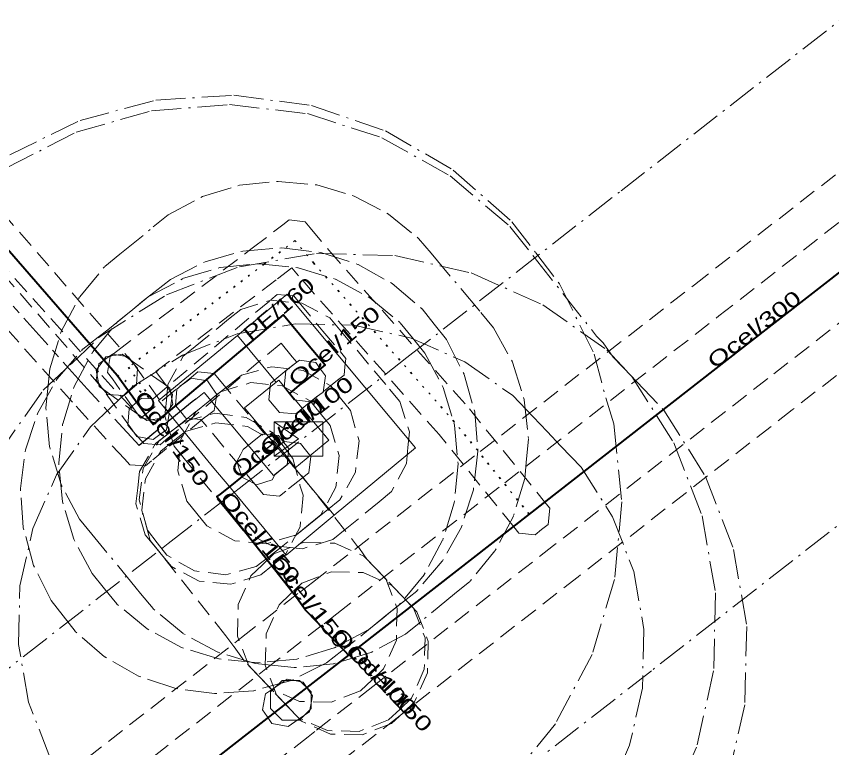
# Model space of a CAD drawing. Extents: x -588392 to -586332, y -1208963 to -1206334.
# Drawn here: x -587903.38 to -587862.35, y -1206828.1 to -1206791.27 of the extents above; entities that cross this region are included whole.
import ezdxf

# ---------------------------------------------------------------- set-up
doc = ezdxf.new("R2010")
doc.units = 0
doc.header["$LTSCALE"] = 0.3
for name, pattern in [('DOT_DASHED', [7.7, 5, -1.2, 0.3, -1.2]), ('DOTTED', [1.5, 0.3, -1.2]), ('LONG_DASH_SHORT_DASH', [9.9, 6, -1.2, 1.5, -1.2]), ('MEDIUM_DASHED', [4.5, 3, -1.5])]:
    doc.linetypes.add(name, pattern=pattern)
for name, color, linetype, lineweight in [('1', 7, 'MEDIUM_DASHED', 13), ('11', 7, 'MEDIUM_DASHED', 13), ('24', 7, 'Continuous', 25), ('3', 7, 'DOT_DASHED', 13), ('31', 7, 'Continuous', 13), ('34', 7, 'Continuous', 40), ('35', 7, 'Continuous', 35), ('51', 7, 'MEDIUM_DASHED', 13), ('54', 7, 'Continuous', 13), ('55', 7, 'LONG_DASH_SHORT_DASH', 25), ('56', 7, 'DOTTED', 35), ('59', 7, 'Continuous', 13), ('7', 7, 'MEDIUM_DASHED', 13), ('8', 7, 'MEDIUM_DASHED', 13)]:
    doc.layers.add(name, color=color, linetype=linetype, lineweight=lineweight)
doc.layers.add('30', color=7, linetype='Continuous')
doc.layers.add('40', color=7, linetype='Continuous')

msp = doc.modelspace()

# ---------------------------------------------------------------- linework, layer by layer
at = {"layer": '1'}
for points in [[(-587903, -1206831.106), (-587892.392, -1206822.823), (-587892.049, -1206822.555), (-587889.13, -1206820.281), (-587888.482, -1206819.776), (-587880.036, -1206813.19), (-587869.26, -1206804.786), (-587825.045, -1206770.304)], [(-587819.53, -1206776.148), (-587864.34, -1206811.094), (-587875.116, -1206819.498), (-587883.564, -1206826.086), (-587884.212, -1206826.591), (-587887.131, -1206828.865)]]:
    msp.add_lwpolyline(points, dxfattribs=at)
for points in [[(-587926.025, -1206775.891), (-587925.751, -1206776.201), (-587925.351, -1206776.654), (-587897.549, -1206808.683), (-587897.277, -1206808.996), (-587897.335, -1206809.823), (-587897.648, -1206810.094), (-587897.961, -1206810.366), (-587898.788, -1206810.308), (-587899.059, -1206809.995), (-587926.857, -1206777.972), (-587927.251, -1206777.525), (-587927.525, -1206777.214), (-587927.473, -1206776.387), (-587927.163, -1206776.113), (-587926.852, -1206775.839)], [(-587897.082, -1206810.493), (-587896.505, -1206810.534), (-587890.574, -1206805.545), (-587890.254, -1206805.276), (-587889.838, -1206805.314), (-587889.423, -1206805.352), (-587889.157, -1206805.675), (-587887.962, -1206807.129), (-587887.077, -1206808.173), (-587886.803, -1206808.496), (-587886.845, -1206808.918), (-587886.886, -1206809.339), (-587887.217, -1206809.602), (-587888.247, -1206810.422), (-587888.571, -1206810.68), (-587889.394, -1206810.587), (-587889.652, -1206810.263), (-587889.91, -1206809.939), (-587889.817, -1206809.116), (-587889.493, -1206808.858), (-587889.27, -1206808.68), (-587889.498, -1206808.411), (-587890.06, -1206807.726), (-587895.836, -1206812.585), (-587896.15, -1206812.849), (-587896.967, -1206812.785), (-587897.236, -1206812.475), (-587897.496, -1206812.175), (-587897.767, -1206811.862), (-587897.708, -1206811.035), (-587897.395, -1206810.764)], [(-587897.732, -1206808.42), (-587897.491, -1206808.756), (-587895.927, -1206810.937), (-587895.686, -1206811.274), (-587895.821, -1206812.092), (-587896.157, -1206812.333), (-587896.494, -1206812.574), (-587897.312, -1206812.439), (-587897.553, -1206812.103), (-587899.117, -1206809.922), (-587899.358, -1206809.585), (-587899.223, -1206808.767), (-587898.887, -1206808.526), (-587898.55, -1206808.285)], [(-587887.939, -1206810.191), (-587888.27, -1206810.44), (-587888.529, -1206810.634), (-587888.998, -1206811.027), (-587889.316, -1206811.293), (-587890.141, -1206811.22), (-587890.407, -1206810.902), (-587890.673, -1206810.584), (-587890.6, -1206809.759), (-587890.282, -1206809.493), (-587889.771, -1206809.066), (-587889.47, -1206808.84), (-587889.139, -1206808.591), (-587888.319, -1206808.709), (-587888.07, -1206809.04), (-587887.821, -1206809.371)], [(-587887.096, -1206815.625), (-587887.72, -1206816.118), (-587888.211, -1206816.506), (-587888.315, -1206816.589), (-587888.671, -1206816.879), (-587889.288, -1206817.382), (-587890.812, -1206817.84), (-587892.395, -1206817.679), (-587893.796, -1206816.925), (-587894.299, -1206816.309), (-587894.802, -1206815.692), (-587895.26, -1206814.168), (-587895.099, -1206812.585), (-587894.345, -1206811.184), (-587893.729, -1206810.681), (-587893.325, -1206810.351), (-587893.171, -1206810.23), (-587892.68, -1206809.842), (-587892.056, -1206809.349), (-587890.525, -1206808.915), (-587888.945, -1206809.1), (-587887.555, -1206809.876), (-587887.062, -1206810.5), (-587886.569, -1206811.124), (-587886.135, -1206812.655), (-587886.32, -1206814.235)], [(-587888.056, -1206816.378), (-587888.673, -1206816.881), (-587890.06, -1206818.011), (-587890.678, -1206818.49), (-587891.307, -1206818.978), (-587892.841, -1206819.398), (-587894.42, -1206819.199), (-587895.802, -1206818.411), (-587896.29, -1206817.782), (-587896.778, -1206817.153), (-587897.198, -1206815.619), (-587896.999, -1206814.04), (-587896.211, -1206812.658), (-587895.582, -1206812.17), (-587895.04, -1206811.749), (-587893.727, -1206810.679), (-587893.11, -1206810.176), (-587891.586, -1206809.72), (-587890.003, -1206809.881), (-587888.602, -1206810.636), (-587888.099, -1206811.253), (-587887.596, -1206811.87), (-587887.14, -1206813.394), (-587887.301, -1206814.977)], [(-587889.47, -1206813.532), (-587889.111, -1206814.88), (-587888.953, -1206815.391), (-587889.102, -1206816.976), (-587889.845, -1206818.382), (-587890.458, -1206818.89), (-587891.071, -1206819.398), (-587892.591, -1206819.867), (-587894.176, -1206819.718), (-587895.582, -1206818.975), (-587896.09, -1206818.362), (-587896.38, -1206818.012), (-587896.901, -1206817.384), (-587897.366, -1206815.82), (-587897.274, -1206815.009), (-587897.182, -1206814.198), (-587896.378, -1206812.778), (-587895.73, -1206812.283), (-587895.56, -1206812.153), (-587894.928, -1206811.67), (-587893.39, -1206811.26), (-587891.813, -1206811.47), (-587890.436, -1206812.268), (-587889.953, -1206812.9)], [(-587892.424, -1206823.023), (-587892.439, -1206823.002), (-587892.842, -1206822.47), (-587896.147, -1206818.291), (-587896.641, -1206817.667), (-587897.075, -1206816.136), (-587896.891, -1206814.556), (-587896.115, -1206813.167), (-587895.491, -1206812.673), (-587894.867, -1206812.179), (-587893.336, -1206811.745), (-587891.756, -1206811.929), (-587890.367, -1206812.705), (-587889.873, -1206813.329), (-587886.518, -1206817.57), (-587886.217, -1206817.967), (-587886.154, -1206818.029), (-587885.896, -1206818.397), (-587885.742, -1206818.612), (-587885.345, -1206819.029), (-587884.796, -1206819.605), (-587884.222, -1206821.089), (-587884.26, -1206822.68), (-587884.904, -1206824.135), (-587885.48, -1206824.684), (-587886.056, -1206825.233), (-587887.54, -1206825.807), (-587889.131, -1206825.769), (-587890.586, -1206825.125), (-587891.135, -1206824.549), (-587891.918, -1206823.728)], [(-587889.181, -1206826.599), (-587889.73, -1206826.023), (-587890.428, -1206825.291), (-587891.136, -1206824.548), (-587891.685, -1206823.972), (-587892.258, -1206822.488), (-587892.219, -1206820.897), (-587891.575, -1206819.442), (-587890.999, -1206818.893), (-587890.423, -1206818.344), (-587888.939, -1206817.771), (-587887.348, -1206817.81), (-587885.893, -1206818.454), (-587885.344, -1206819.03), (-587884.638, -1206819.771), (-587883.94, -1206820.503), (-587883.391, -1206821.079), (-587882.817, -1206822.563), (-587882.855, -1206824.153), (-587883.499, -1206825.609), (-587884.075, -1206826.158), (-587884.651, -1206826.707), (-587886.135, -1206827.281), (-587887.725, -1206827.243)], [(-587889.027, -1206826.765), (-587889.574, -1206826.188), (-587889.738, -1206826.015), (-587890.285, -1206825.438), (-587890.855, -1206823.952), (-587890.812, -1206822.361), (-587890.164, -1206820.907), (-587889.587, -1206820.36), (-587889.01, -1206819.813), (-587887.524, -1206819.243), (-587885.933, -1206819.286), (-587884.479, -1206819.934), (-587883.932, -1206820.511), (-587883.768, -1206820.684), (-587883.221, -1206821.261), (-587882.651, -1206822.747), (-587882.694, -1206824.338), (-587883.342, -1206825.792), (-587883.919, -1206826.339), (-587884.496, -1206826.886), (-587885.982, -1206827.456), (-587887.573, -1206827.413)]]:
    msp.add_lwpolyline(points, close=True, dxfattribs=at)
at = {"layer": '1', "linetype": 'DOT_DASHED'}
for points in [[(-587903.714, -1206798.246), (-587900.178, -1206796.51), (-587896.371, -1206795.496), (-587892.439, -1206795.245), (-587888.534, -1206795.766), (-587884.806, -1206797.038), (-587881.397, -1206799.014), (-587878.44, -1206801.616), (-587877.243, -1206803.181), (-587876.046, -1206804.746), (-587874.31, -1206808.282), (-587873.725, -1206810.478), (-587873.318, -1206811.797), (-587872.914, -1206815.716), (-587873.281, -1206819.638), (-587874.407, -1206823.413), (-587876.248, -1206826.896), (-587878.733, -1206829.953)], [(-587903.872, -1206798.902), (-587900.365, -1206797.108), (-587896.575, -1206796.032), (-587892.648, -1206795.716), (-587888.735, -1206796.173), (-587884.986, -1206797.385), (-587881.546, -1206799.304), (-587878.546, -1206801.858), (-587877.324, -1206803.403), (-587874.183, -1206807.373), (-587873.85, -1206807.706), (-587873.342, -1206808.432), (-587872.404, -1206809.416), (-587870.294, -1206812.743), (-587868.874, -1206816.418), (-587868.199, -1206820.299), (-587868.293, -1206824.238), (-587869.154, -1206828.082), (-587870.749, -1206831.685)], [(-587906.215, -1206828.582), (-587906.881, -1206824.698), (-587906.775, -1206820.76), (-587905.904, -1206816.918), (-587904.3, -1206813.319), (-587902.025, -1206810.103), (-587900.595, -1206808.748), (-587899.165, -1206807.393), (-587895.832, -1206805.292), (-587892.154, -1206803.883), (-587888.27, -1206803.217), (-587884.332, -1206803.323), (-587880.49, -1206804.194), (-587876.891, -1206805.798), (-587873.675, -1206808.073), (-587872.32, -1206809.503), (-587872.156, -1206809.676), (-587870.801, -1206811.106), (-587868.7, -1206814.439), (-587867.291, -1206818.117), (-587866.625, -1206822.001), (-587866.731, -1206825.939), (-587867.602, -1206829.781)], [(-587901.701, -1206828.571), (-587902.765, -1206825.815), (-587903.271, -1206822.904), (-587903.2, -1206819.95), (-587902.554, -1206817.066), (-587901.357, -1206814.365), (-587899.657, -1206811.948), (-587898.587, -1206810.929), (-587897.517, -1206809.91), (-587895.022, -1206808.328), (-587892.266, -1206807.264), (-587889.355, -1206806.758), (-587886.401, -1206806.829), (-587883.517, -1206807.475), (-587880.816, -1206808.672), (-587878.399, -1206810.372), (-587877.38, -1206811.442), (-587876.675, -1206812.182), (-587875.979, -1206812.912), (-587874.96, -1206813.981), (-587873.377, -1206816.476), (-587872.312, -1206819.232), (-587871.804, -1206822.143), (-587871.875, -1206825.097), (-587872.52, -1206827.98), (-587873.715, -1206830.682)]]:
    msp.add_lwpolyline(points, dxfattribs=at)
for points in [[(-587883.227, -1206820.215), (-587884, -1206820.826), (-587884.49, -1206821.213), (-587884.558, -1206821.267), (-587884.879, -1206821.529), (-587885.642, -1206822.152), (-587887.382, -1206823.075), (-587889.269, -1206823.641), (-587891.229, -1206823.828), (-587893.189, -1206823.63), (-587895.073, -1206823.052), (-587896.807, -1206822.118), (-587898.326, -1206820.864), (-587898.949, -1206820.101), (-587899.572, -1206819.338), (-587900.495, -1206817.598), (-587901.061, -1206815.711), (-587901.248, -1206813.751), (-587901.05, -1206811.791), (-587900.472, -1206809.907), (-587899.538, -1206808.173), (-587898.284, -1206806.654), (-587897.521, -1206806.031), (-587897.082, -1206805.673), (-587896.892, -1206805.523), (-587896.4, -1206805.134), (-587895.627, -1206804.523), (-587893.873, -1206803.627), (-587891.978, -1206803.09), (-587890.014, -1206802.933), (-587888.058, -1206803.163), (-587886.184, -1206803.769), (-587884.464, -1206804.73), (-587882.965, -1206806.007), (-587882.354, -1206806.78), (-587881.743, -1206807.553), (-587880.847, -1206809.307), (-587880.31, -1206811.202), (-587880.153, -1206813.166), (-587880.383, -1206815.122), (-587880.989, -1206816.996), (-587881.95, -1206818.716)], [(-587884.119, -1206820.91), (-587884.883, -1206821.532), (-587886.326, -1206822.708), (-587887, -1206823.231), (-587887.778, -1206823.835), (-587889.54, -1206824.715), (-587891.44, -1206825.235), (-587893.405, -1206825.375), (-587895.359, -1206825.128), (-587897.228, -1206824.505), (-587898.939, -1206823.529), (-587900.427, -1206822.238), (-587901.031, -1206821.46), (-587901.635, -1206820.682), (-587902.515, -1206818.92), (-587903.035, -1206817.02), (-587903.175, -1206815.055), (-587902.928, -1206813.101), (-587902.305, -1206811.232), (-587901.329, -1206809.521), (-587900.038, -1206808.033), (-587899.26, -1206807.429), (-587898.774, -1206807.052), (-587897.517, -1206806.028), (-587896.753, -1206805.406), (-587895.013, -1206804.483), (-587893.126, -1206803.918), (-587891.165, -1206803.732), (-587889.205, -1206803.932), (-587887.322, -1206804.51), (-587885.588, -1206805.445), (-587884.07, -1206806.699), (-587883.448, -1206807.463), (-587882.826, -1206808.227), (-587881.903, -1206809.967), (-587881.338, -1206811.854), (-587881.152, -1206813.815), (-587881.352, -1206815.775), (-587881.93, -1206817.658), (-587882.865, -1206819.392)]]:
    msp.add_lwpolyline(points, close=True, dxfattribs=at)
at = {"layer": '11'}
msp.add_lwpolyline([(-587891.213, -1206815.038), (-587894.092, -1206811.58), (-587894.847, -1206811.51), (-587895.111, -1206811.191), (-587895.376, -1206810.872), (-587895.3, -1206810.047), (-587894.981, -1206809.783), (-587894.569, -1206809.441), (-587894.25, -1206809.177), (-587893.426, -1206809.252), (-587893.161, -1206809.57), (-587890.302, -1206813.006), (-587890.229, -1206812.948), (-587889.905, -1206812.69), (-587889.082, -1206812.783), (-587888.824, -1206813.107), (-587888.566, -1206813.431), (-587888.659, -1206814.254), (-587888.983, -1206814.512), (-587889.821, -1206815.18), (-587890.14, -1206815.434), (-587890.952, -1206815.351)], close=True, dxfattribs=at)
at = {"layer": '24', "lineweight": 40}
msp.add_line((-587898.304, -1206809.339), (-587896.74, -1206811.52), dxfattribs=at)
for points in [[(-587926.501, -1206776.863), (-587926.104, -1206777.313), (-587898.304, -1206809.339)], [(-587896.74, -1206811.52), (-587896.48, -1206811.82), (-587889.93, -1206806.31), (-587888.73, -1206807.77), (-587887.84, -1206808.82), (-587888.87, -1206809.64)], [(-587888.87, -1206809.64), (-587889.15, -1206809.85), (-587889.64, -1206810.26)]]:
    msp.add_lwpolyline(points, dxfattribs=at)
at = {"layer": '3'}
msp.add_lwpolyline([(-587898.935, -1206803.874), (-587898.17, -1206803.25), (-587896.49, -1206801.88), (-587895.734, -1206801.263), (-587894.011, -1206800.346), (-587892.144, -1206799.778), (-587890.202, -1206799.582), (-587888.258, -1206799.766), (-587886.387, -1206800.322), (-587884.659, -1206801.229), (-587883.139, -1206802.453), (-587882.511, -1206803.2), (-587880.001, -1206806.19), (-587879.363, -1206806.951), (-587878.41, -1206808.693), (-587877.819, -1206810.588), (-587877.611, -1206812.563), (-587877.703, -1206813.551), (-587877.795, -1206814.539), (-587878.365, -1206816.441), (-587879.298, -1206818.194), (-587880.557, -1206819.729), (-587881.325, -1206820.358), (-587883.035, -1206821.758), (-587883.799, -1206822.383), (-587885.541, -1206823.31), (-587887.431, -1206823.88), (-587889.395, -1206824.068), (-587890.377, -1206823.969), (-587891.359, -1206823.87), (-587893.245, -1206823.291), (-587894.982, -1206822.355), (-587896.503, -1206821.097), (-587897.126, -1206820.332), (-587897.347, -1206820.061), (-587899.575, -1206817.35), (-587900.202, -1206816.587), (-587901.134, -1206814.846), (-587901.707, -1206812.956), (-587901.899, -1206810.99), (-587901.801, -1206810.008), (-587901.703, -1206809.026), (-587901.127, -1206807.137), (-587900.192, -1206805.397)], close=True, dxfattribs=at)
at = {"layer": '3', "linetype": 'MEDIUM_DASHED'}
msp.add_lwpolyline([(-587894.996, -1206808.404), (-587894.378, -1206807.9), (-587892.698, -1206806.53), (-587892.087, -1206806.032), (-587890.579, -1206805.574), (-587889.009, -1206805.722), (-587887.613, -1206806.454), (-587887.106, -1206807.058), (-587884.596, -1206810.048), (-587884.081, -1206810.662), (-587883.603, -1206812.193), (-587883.677, -1206812.992), (-587883.752, -1206813.791), (-587884.505, -1206815.207), (-587885.126, -1206815.715), (-587886.836, -1206817.115), (-587887.453, -1206817.62), (-587888.98, -1206818.08), (-587889.773, -1206818), (-587890.566, -1206817.92), (-587891.969, -1206817.163), (-587892.472, -1206816.545), (-587892.702, -1206816.262), (-587894.94, -1206813.54), (-587895.447, -1206812.924), (-587895.909, -1206811.397), (-587895.83, -1206810.603), (-587895.751, -1206809.809)], close=True, dxfattribs=at)
at = {"layer": '31'}
msp.add_lwpolyline([(-587890.408, -1206811.687), (-587887.958, -1206811.687), (-587887.958, -1206813.419), (-587890.408, -1206813.419)], dxfattribs=at)
msp.add_lwpolyline([(-587890.408, -1206811.687), (-587889.183, -1206812.553), (-587890.408, -1206813.419)], close=True, dxfattribs=at)
at = {"layer": '34'}
msp.add_line((-587886.671, -1206823.436), (-587886.835, -1206823.263), dxfattribs=at)
for points in [[(-587822.287, -1206773.226), (-587866.8, -1206807.94), (-587877.576, -1206816.344), (-587886.023, -1206822.931), (-587886.671, -1206823.436), (-587889.59, -1206825.71), (-587889.931, -1206825.976), (-587900.54, -1206834.26), (-587906.344, -1206838.782), (-587909.5, -1206841.24), (-587910.49, -1206842.01), (-587912.678, -1206844.739), (-587912.978, -1206845.114), (-587913.309, -1206845.527), (-587913.36, -1206845.59)], [(-587890.2, -1206812.98), (-587890.691, -1206813.368), (-587890.82, -1206813.47), (-587891.2, -1206813.78)], [(-587891.2, -1206813.78), (-587892.55, -1206814.88), (-587893.13, -1206815.33)], [(-587893.13, -1206815.33), (-587893.3, -1206815.46), (-587893.01, -1206815.81)], [(-587888.24, -1206821.789), (-587888.83, -1206821.17), (-587889.16, -1206820.71), (-587889.23, -1206820.61), (-587889.24, -1206820.6), (-587889.68, -1206820.02), (-587893.01, -1206815.81)], [(-587886.835, -1206823.263), (-587887.533, -1206822.531), (-587888.24, -1206821.789)]]:
    msp.add_lwpolyline(points, dxfattribs=at)
at = {"layer": '35'}
msp.add_lwpolyline([(-587822.287, -1206773.226), (-587866.8, -1206807.94), (-587877.576, -1206816.344), (-587886.023, -1206822.931), (-587886.671, -1206823.436), (-587889.59, -1206825.71), (-587889.931, -1206825.976), (-587900.54, -1206834.26), (-587906.344, -1206838.782), (-587909.5, -1206841.24), (-587910.49, -1206842.01), (-587912.678, -1206844.739), (-587912.978, -1206845.114), (-587913.309, -1206845.527), (-587913.36, -1206845.59)], dxfattribs=at)
at = {"layer": '51', "linetype": 'DOT_DASHED'}
for points in [[(-587912.489, -1206830.893), (-587906.69, -1206826.375), (-587896.084, -1206818.093), (-587895.738, -1206817.823), (-587892.817, -1206815.548), (-587892.171, -1206815.044), (-587883.726, -1206808.458), (-587872.95, -1206800.055), (-587829.182, -1206765.921)], [(-587860.65, -1206815.825), (-587871.426, -1206824.23), (-587879.875, -1206830.818)]]:
    msp.add_lwpolyline(points, dxfattribs=at)
at = {"layer": '51'}
for points in [[(-587901.77, -1206832.683), (-587891.162, -1206824.399), (-587890.82, -1206824.133), (-587887.9, -1206821.858), (-587887.253, -1206821.354), (-587878.806, -1206814.767), (-587868.03, -1206806.363), (-587823.666, -1206771.765)], [(-587820.909, -1206774.686), (-587865.57, -1206809.517), (-587876.346, -1206817.921), (-587884.793, -1206824.508), (-587885.442, -1206825.014), (-587888.36, -1206827.287), (-587888.7, -1206827.553), (-587899.31, -1206835.837)]]:
    msp.add_lwpolyline(points, dxfattribs=at)
at = {"layer": '54'}
for p, q in [((-587892.26, -1206807.34), (-587889.76, -1206805.27)), ((-587889.76, -1206805.27), (-587883.29, -1206813)), ((-587890.34, -1206809.66), (-587890.31, -1206809.696)), ((-587887.66, -1206812.62), (-587889.37, -1206814.02)), ((-587887.839, -1206812.404), (-587887.81, -1206812.38)), ((-587883.29, -1206813), (-587887.39, -1206816.4)), ((-587889.5, -1206813.93), (-587889.467, -1206813.903)), ((-587889.37, -1206814.02), (-587887.39, -1206816.4)), ((-587889.8, -1206818.41), (-587892.69, -1206814.92)), ((-587887.39, -1206816.4), (-587889.8, -1206818.41))]:
    msp.add_line(p, q, dxfattribs=at)
for points in [[(-587896.23, -1206810.62), (-587892.26, -1206807.34), (-587890.34, -1206809.66)], [(-587891.893, -1206810.989), (-587890.31, -1206809.696), (-587890.18, -1206809.59)], [(-587890.18, -1206809.59), (-587887.839, -1206812.404), (-587887.66, -1206812.62)], [(-587892.69, -1206814.92), (-587893.44, -1206814.02), (-587896.23, -1206810.62)], [(-587889.37, -1206814.02), (-587889.467, -1206813.903), (-587891.893, -1206810.989)]]:
    msp.add_lwpolyline(points, dxfattribs=at)
at = {"layer": '55'}
msp.add_lwpolyline([(-587894.342, -1206810.552), (-587894.539, -1206810.692), (-587896.46, -1206812.27), (-587897.208, -1206812.884), (-587899.82, -1206810.03), (-587909.61, -1206799.11), (-587921.01, -1206785.93), (-587925.2, -1206780.79)], dxfattribs=at)
at = {"layer": '56'}
msp.add_line((-587898.304, -1206809.339), (-587896.57, -1206810.569), dxfattribs=at)
for points in [[(-587877.576, -1206816.344), (-587881.346, -1206811.685), (-587888.423, -1206803.692), (-587889.363, -1206802.567), (-587890.91, -1206803.745), (-587897.739, -1206808.946), (-587896.57, -1206810.569)], [(-587891.2, -1206813.78), (-587891.172, -1206813.726), (-587890.704, -1206813.343)], [(-587889.59, -1206825.71), (-587889.54, -1206825.71), (-587889.931, -1206825.976)]]:
    msp.add_lwpolyline(points, dxfattribs=at)
at = {"layer": '59'}
msp.add_lwpolyline([(-587894.342, -1206810.552), (-587893.93, -1206810.21), (-587890.444, -1206814.398), (-587889.606, -1206813.73)], dxfattribs=at)
at = {"layer": '7'}
msp.add_lwpolyline([(-587920.244, -1206785.287), (-587908.859, -1206798.449), (-587899.079, -1206809.359), (-587897.11, -1206811.51), (-587897.095, -1206811.497), (-587895.147, -1206809.897), (-587894.921, -1206809.737), (-587894.583, -1206809.497), (-587893.767, -1206809.635), (-587893.527, -1206809.973), (-587893.287, -1206810.311), (-587893.425, -1206811.127), (-587893.763, -1206811.367), (-587893.931, -1206811.487), (-587895.825, -1206813.043), (-587896.574, -1206813.657), (-587896.882, -1206813.91), (-587897.677, -1206813.853), (-587897.946, -1206813.559), (-587900.561, -1206810.701), (-587910.361, -1206799.771), (-587921.776, -1206786.573)], dxfattribs=at)
at = {"layer": '8'}
for points in [[(-587878.092, -1206817.295), (-587878.353, -1206816.973), (-587882.109, -1206812.331), (-587889.181, -1206804.344), (-587889.518, -1206803.942), (-587890.304, -1206804.541), (-587896.359, -1206809.152), (-587895.759, -1206809.985), (-587895.517, -1206810.321), (-587895.65, -1206811.138), (-587895.986, -1206811.38), (-587896.322, -1206811.622), (-587897.139, -1206811.489), (-587897.381, -1206811.153), (-587898.55, -1206809.53), (-587898.788, -1206809.2), (-587898.668, -1206808.396), (-587898.345, -1206808.15), (-587891.516, -1206802.949), (-587889.969, -1206801.771), (-587889.65, -1206801.528), (-587888.853, -1206801.618), (-587888.596, -1206801.926), (-587887.665, -1206803.04), (-587880.583, -1206811.039), (-587876.799, -1206815.715), (-587876.538, -1206816.037), (-587876.625, -1206816.86), (-587876.947, -1206817.121), (-587877.269, -1206817.382)], [(-587898.063, -1206808.284), (-587897.725, -1206808.523), (-587895.991, -1206809.753), (-587895.653, -1206809.993), (-587895.515, -1206810.81), (-587895.754, -1206811.148), (-587895.994, -1206811.486), (-587896.811, -1206811.624), (-587897.149, -1206811.385), (-587898.883, -1206810.155), (-587899.221, -1206809.915), (-587899.359, -1206809.098), (-587899.12, -1206808.76), (-587898.88, -1206808.422)], [(-587890.071, -1206814.117), (-587890.379, -1206814.369), (-587890.503, -1206814.608), (-587891.293, -1206814.859), (-587891.66, -1206814.668), (-587892.028, -1206814.477), (-587892.279, -1206813.687), (-587892.088, -1206813.32), (-587891.965, -1206813.083), (-587891.337, -1206812.569), (-587891.016, -1206812.307), (-587890.192, -1206812.389), (-587889.93, -1206812.71), (-587889.668, -1206813.031), (-587889.75, -1206813.855)], [(-587888.635, -1206826.304), (-587888.978, -1206826.537), (-587889.369, -1206826.803), (-587889.711, -1206827.036), (-587890.525, -1206826.881), (-587890.758, -1206826.538), (-587890.991, -1206826.196), (-587890.836, -1206825.382), (-587890.493, -1206825.149), (-587890.102, -1206824.883), (-587889.76, -1206824.65), (-587888.946, -1206824.805), (-587888.713, -1206825.148), (-587888.48, -1206825.49)], [(-587890.004, -1206824.71), (-587889.59, -1206824.71), (-587889.54, -1206824.71), (-587889.126, -1206824.71), (-587888.54, -1206825.296), (-587888.54, -1206825.71), (-587888.54, -1206826.124), (-587889.126, -1206826.71), (-587889.54, -1206826.71), (-587889.59, -1206826.71), (-587890.004, -1206826.71), (-587890.59, -1206826.124), (-587890.59, -1206825.71), (-587890.59, -1206825.296)]]:
    msp.add_lwpolyline(points, close=True, dxfattribs=at)

# ---------------------------------------------------------------- texts
at = {"layer": '30'}
for s, rotation, width, p in [('PE/160', 40.071, 1.3, (-587891.565, -1206807.685)), ('Ocel/150', 39.92, 1.4, (-587889.299, -1206809.975)), ('Ocel/150', 305.644, 1.4, (-587897.493, -1206810.47))]:
    msp.add_text(s, height=0.75, rotation=rotation, dxfattribs=dict(at, width=width)).set_placement(p)
at = {"layer": '40', "width": 1.4}
for s, rotation, p in [('Ocel/300', 37.95, (-587868.237, -1206809.06)), ('Ocel/100', 38.333, (-587890.742, -1206813.408)), ('Ocel/100', 39.174, (-587892.199, -1206814.593)), ('Ocel/150', 309.644, (-587893.191, -1206815.591)), ('Ocel/150', 308.343, (-587890.667, -1206818.772)), ('Ocel/100', 313.616, (-587887.572, -1206822.49)), ('Ocel/150', 313.47, (-587886.787, -1206823.313))]:
    msp.add_text(s, height=0.75, rotation=rotation, dxfattribs=at).set_placement(p)

doc.saveas('drawing.dxf')
